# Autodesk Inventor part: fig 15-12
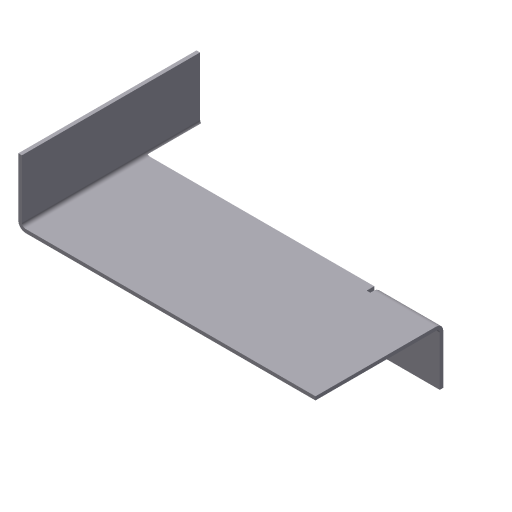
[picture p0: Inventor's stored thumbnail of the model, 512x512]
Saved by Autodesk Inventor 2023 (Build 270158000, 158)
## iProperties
Created: 2002-04
Part Number: fig 15-12
Material: Aluminum-6061
Document SubType Name: Sheet Metal
Density: 1 g/cm^3
Sheet Metal Rule: Default
Appearance: Aluminum - Flat-1
Control State: 0
Master: False
Checked Out: False
Shininess: 77.0
Angle Display Precision: 2
Document Length Units: 11269
Document Angle Units: 11279
Document Time Units: 11290
Document Mass Units: 11283
Document Length Units Precision: 3
Document Angle Units Precision: 2
Density: 0.0
Volumn: 0.0
Area: 0.0
PropertySet Name: Model Information
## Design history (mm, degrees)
node "Face1"
  sketch "Sketch1"
    geometry: L1 (-49.559, 19.574)-(-49.559, -30.426); L2 (-49.559, -30.426)-(50.441, -30.426); L3 (50.441, -30.426)-(50.441, 19.574); L4 (50.441, 19.574)-(32.941, 19.574); L5 (32.941, 19.574)-(32.941, 4.574); L6 (32.941, 4.574)-(-32.059, 4.574); L7 (-32.059, 4.574)-(-32.059, 19.574); L8 (-32.059, 19.574)-(-49.559, 19.574)
    constraints: 16 end point, 6 parallel, 2 equal length, 1 perpendicular, 1 vertical
    dimensions: "d0" = 100 distance of L1.end L2.end; "d1" = 65 distance of L5.end L6.end; "d2" = 15 distance of L6.end L7.end; "d3" = 50 distance of L1.start L1.end
sketch "Sketch2"
  geometry: L1 (100, 0)-(0, 0) reference; L2 (17.5, 50)-(17.5, 35) reference; L3 (82.5, 50)-(82.5, 0)
  constraints: 2 end point, 1 parallel, 1 point on line
sketch "Sketch3"
  geometry: L1 (81.369, -50)-(0, -50) reference; L2 (17.5, 0)-(17.5, -50)
  constraints: 2 end point, 1 perpendicular, 1 point on line
feature "Fold2" sketch "Sketch3" dims "d8" = 1 (= BendRadius), "d9" = 90 deg, "d10" = 1 (= BendRadius), "d14" = 1 (= BendReliefWidth), "d15" = 0.5 (= BendReliefDepth), "d16" = 2 (= MinimumRemnant), "d20" = 1 (= Thickness), "SeamGap" = 0.01
sketch "Sketch4"
  geometry: L1 (17.5, 0)-(17.5, -50) reference; L2 (-63.869, -15)-(0, -15) reference; L3 (0, -15)-(17.5, -15)
  constraints: 2 end point, 1 collinear, 1 point on line
feature "Fold3" sketch "Sketch4" dims "d11" = 1 (= BendRadius), "d12" = 90 deg, "d13" = 1, "d17" = 1 (= BendReliefWidth), "d18" = 1, "d19" = 2 (= MinimumRemnant), "d20" = 1 (= Thickness), "SeamGap" = 0.01
body "Solid1"
face "Plate1" dims "d20" = 1 (= Thickness)
other parameters: "Thickness" = 1, "BendRadius" = 1 (= Thickness), "BendReliefWidth" = 1 (= Thickness), "BendReliefDepth" = 0.5 (= 0.5 x Thickness), "CornerReliefSize" = 4 (= 4 x Thickness), "MinimumRemnant" = 2 (= 2 x Thickness), "TransitionRadius" = 1 (= BendRadius), "d4" = 1 (= BendRadius), "JacobiRadiusSize" = 1 (= Thickness), "GapSize" = 1 (= Thickness)
